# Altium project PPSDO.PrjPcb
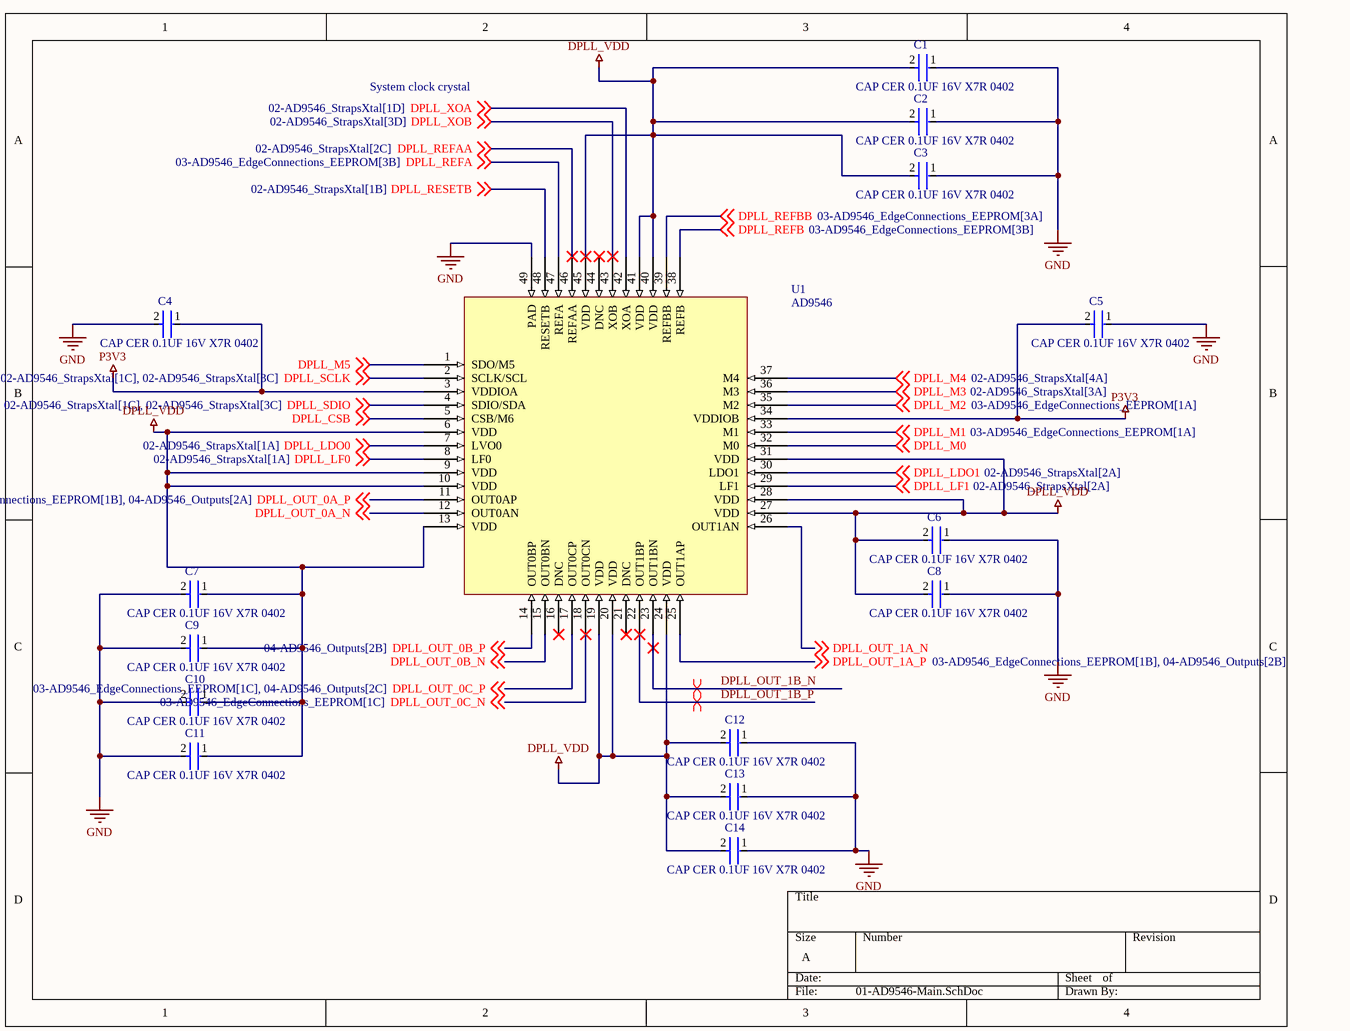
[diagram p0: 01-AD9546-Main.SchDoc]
5 sheets, 74 parts. Net scope: global (net labels, ports and power ports of the same name join across sheets).
Board file: PPSDO.PcbDoc
Sheets:
  01-AD9546-Main.SchDoc
  02-AD9546_StrapsXtal.SchDoc
  03-AD9546_EdgeConnections_EEPROM.SchDoc
  04-AD9546_Outputs.SchDoc
  05-Power.SchDoc

## Sheet 01-AD9546-Main.SchDoc
size A; SheetNumber: 4; SheetTotal: 16

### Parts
C1  GRM155R71C104KA88D  [FP-GRM15-MFG]  (value not drawn)
C2  GRM155R71C104KA88D  [FP-GRM15-MFG]  (value not drawn)
C3  GRM155R71C104KA88D  [FP-GRM15-MFG]  (value not drawn)
C4  GRM155R71C104KA88D  [FP-GRM15-MFG]  (value not drawn)
C5  GRM155R71C104KA88D  [FP-GRM15-MFG]  (value not drawn)
C6  GRM155R71C104KA88D  [FP-GRM15-MFG]  (value not drawn)
C7  GRM155R71C104KA88D  [FP-GRM15-MFG]  (value not drawn)
C8  GRM155R71C104KA88D  [FP-GRM15-MFG]  (value not drawn)
C9  GRM155R71C104KA88D  [FP-GRM15-MFG]  (value not drawn)
C10  GRM155R71C104KA88D  [FP-GRM15-MFG]  (value not drawn)
C11  GRM155R71C104KA88D  [FP-GRM15-MFG]  (value not drawn)
C12  GRM155R71C104KA88D  [FP-GRM15-MFG]  (value not drawn)
C13  GRM155R71C104KA88D  [FP-GRM15-MFG]  (value not drawn)
C14  GRM155R71C104KA88D  [FP-GRM15-MFG]  (value not drawn)
U1  AD9546  [AD9546]

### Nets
DPLL_VDD: C1.2 C2.2 C3.2 C6.2 C7.1 C8.2 C9.1 C10.1 C11.1 C12.2 C13.2 C14.2 U1.6(VDD) U1.9(VDD) U1.10(VDD) U1.13(VDD) U1.19(VDD) U1.20(VDD) U1.24(VDD) U1.27(VDD) U1.28(VDD) U1.31(VDD) U1.40(VDD) U1.41(VDD) U1.45(VDD)
GND: C1.1 C2.1 C3.1 C4.2 C5.1 C6.1 C7.2 C8.1 C9.2 C10.2 C11.2 C12.1 C13.1 C14.1 U1.49(PAD)
P3V3: C4.1 C5.2 U1.3(VDDIOA) U1.34(VDDIOB)
DPLL_CSB: U1.5(CSB/M6) ; off-sheet DPLL_CSB
DPLL_LDO0: U1.7(LVO0) ; off-sheet DPLL_LDO0
DPLL_LDO1: U1.30(LDO1) ; off-sheet DPLL_LDO1
DPLL_LF0: U1.8(LF0) ; off-sheet DPLL_LF0
DPLL_LF1: U1.29(LF1) ; off-sheet DPLL_LF1
DPLL_M0: U1.32(M0) ; off-sheet DPLL_M0
DPLL_M1: U1.33(M1) ; off-sheet DPLL_M1
DPLL_M2: U1.35(M2) ; off-sheet DPLL_M2
DPLL_M3: U1.36(M3) ; off-sheet DPLL_M3
DPLL_M4: U1.37(M4) ; off-sheet DPLL_M4
DPLL_M5: U1.1(SDO/M5) ; off-sheet DPLL_M5
DPLL_OUT_0A_N: U1.12(OUT0AN) ; off-sheet DPLL_OUT_0A_N
DPLL_OUT_0A_P: U1.11(OUT0AP) ; off-sheet DPLL_OUT_0A_P
DPLL_OUT_0B_N: U1.15(OUT0BN) ; off-sheet DPLL_OUT_0B_N
DPLL_OUT_0B_P: U1.14(OUT0BP) ; off-sheet DPLL_OUT_0B_P
DPLL_OUT_0C_N: U1.18(OUT0CN) ; off-sheet DPLL_OUT_0C_N
DPLL_OUT_0C_P: U1.17(OUT0CP) ; off-sheet DPLL_OUT_0C_P
DPLL_OUT_1A_N: U1.26(OUT1AN) ; off-sheet DPLL_OUT_1A_N
DPLL_OUT_1A_P: U1.25(OUT1AP) ; off-sheet DPLL_OUT_1A_P
DPLL_OUT_1B_N: U1.23(OUT1BN)
DPLL_OUT_1B_P: U1.22(OUT1BP)
DPLL_REFA: U1.47(REFA) ; off-sheet DPLL_REFA
DPLL_REFAA: U1.46(REFAA) ; off-sheet DPLL_REFAA
DPLL_REFB: U1.38(REFB) ; off-sheet DPLL_REFB
DPLL_REFBB: U1.39(REFBB) ; off-sheet DPLL_REFBB
DPLL_RESETB: U1.48(RESETB) ; off-sheet DPLL_RESETB
DPLL_SCLK: U1.2(SCLK/SCL) ; off-sheet DPLL_SCLK
DPLL_SDIO: U1.4(SDIO/SDA) ; off-sheet DPLL_SDIO
DPLL_XOA: U1.42(XOA) ; off-sheet DPLL_XOA
DPLL_XOB: U1.43(XOB) ; off-sheet DPLL_XOB

Not connected (* = marked no-connect by the designer): U1 16(DNC)* 21(DNC)* 44(DNC)*

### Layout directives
differential pair; differential pair class 100ohm: DPLL_OUT_1B_N, DPLL_OUT_1B_P

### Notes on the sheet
- System clock crystal

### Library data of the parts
C1-C14 = CMP-2100-03641-2: CAP CER 0.1UF 16V X7R 0402; Manufacturer: Murata; Standoff Height: 0mm; Tolerance: 10%; Voltage Rating: 16Vdc; Material: Ceramic; Capacitance: 0.10μF; Value: 0.10μF

## Sheet 02-AD9546_StrapsXtal.SchDoc
size A; SheetNumber: 5; SheetTotal: 16
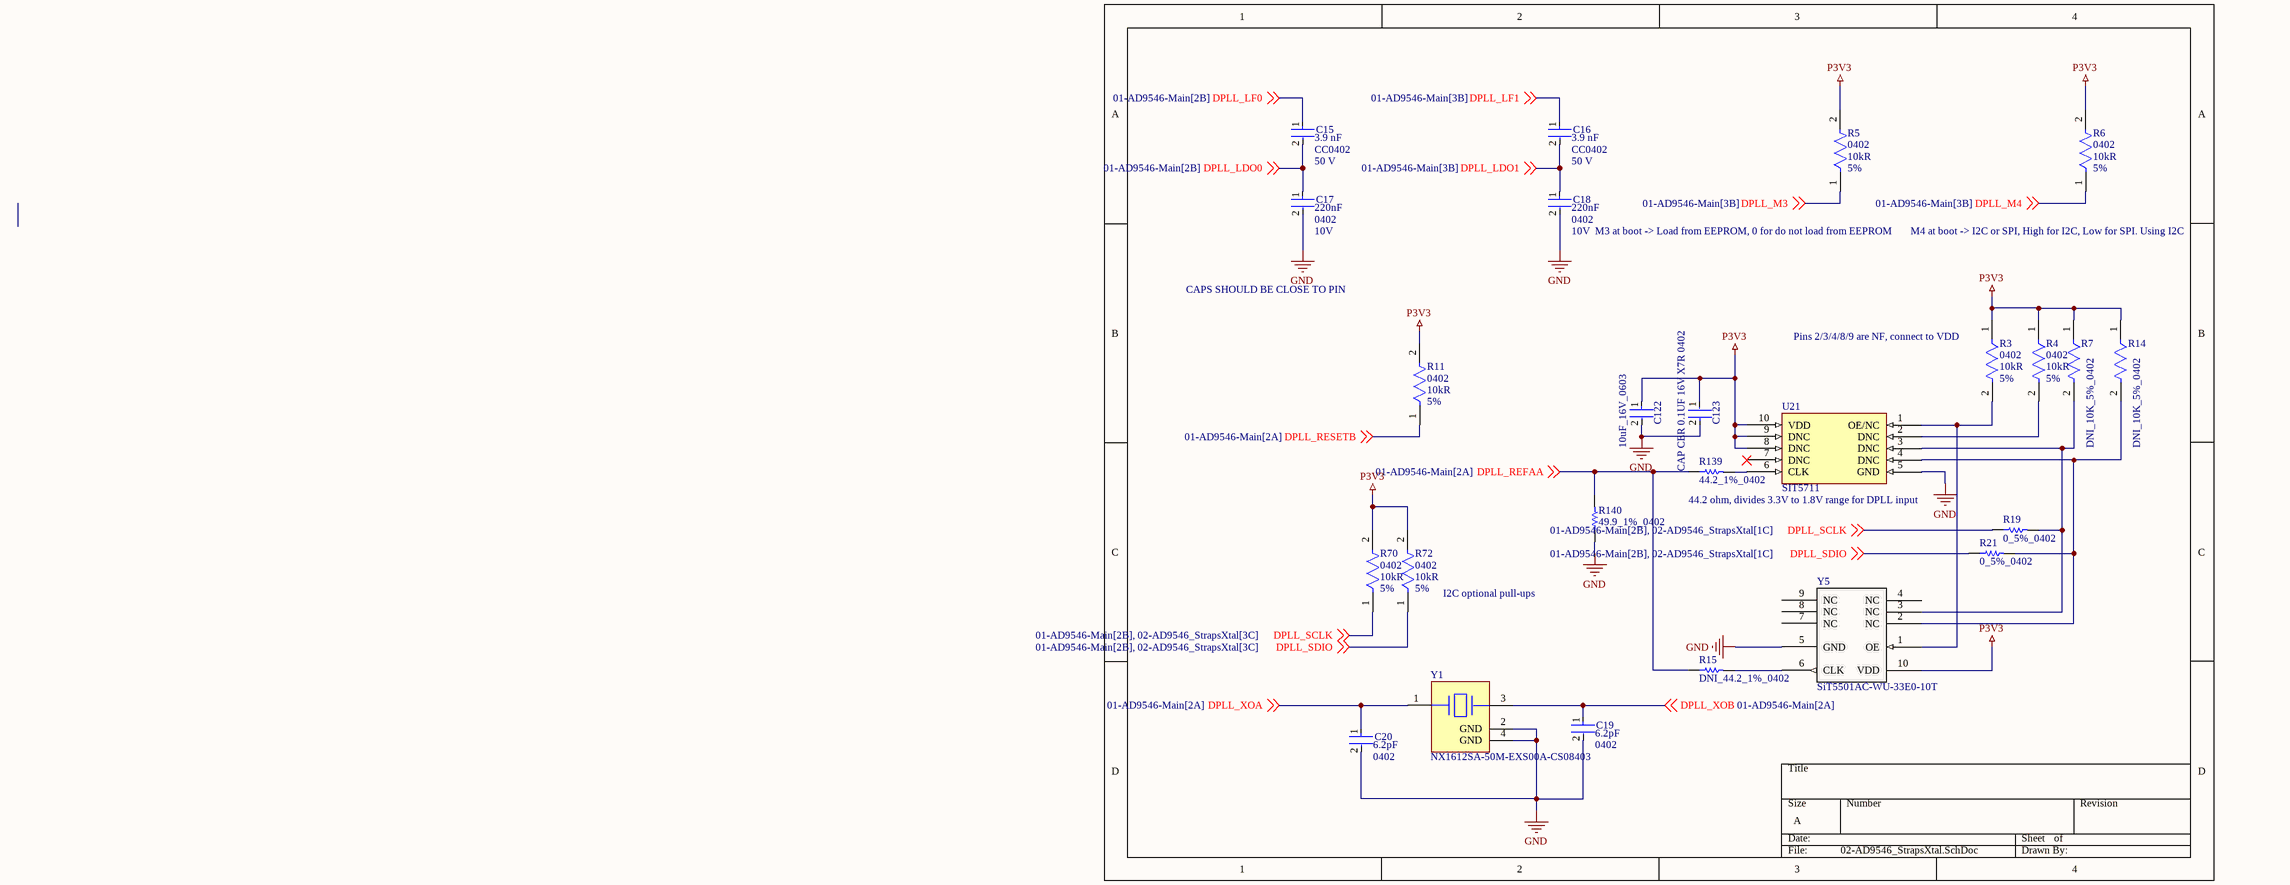
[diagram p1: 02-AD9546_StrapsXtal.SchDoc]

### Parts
C15  value 3.9 nF  Voltage Rating: 50 V  Package: CC0402  [FP-CC0402-MFG]  (hidden comment: CC0402KRX7R9BB392)
C16  value 3.9 nF  Voltage Rating: 50 V  Package: CC0402  [FP-CC0402-MFG]  (hidden comment: CC0402KRX7R9BB392)
C17  Voltage: 10V  Case/Package: 0402  Capacitance: 220nF  [FP-GRM155-0_05-IPC_A]  (hidden comment: GRM155R61A224KE19D)
C18  Voltage: 10V  Case/Package: 0402  Capacitance: 220nF  [FP-GRM155-0_05-IPC_A]  (hidden comment: GRM155R61A224KE19D)
C19  Case/Package: 0402  Capacitance: 6.2pF  [FP-CL468-IPC_C]  (hidden comment: CL05C6R2CB5NNNC)
C20  Case/Package: 0402  Capacitance: 6.2pF  [FP-CL468-IPC_C]  (hidden comment: CL05C6R2CB5NNNC)
C122  10uF_16V_0603  [FP-C1608-MFG]
C123  GRM155R71C104KA88D  [FP-GRM15-MFG]  (value not drawn)
R3  Case/Package: 0402  Resistance: 10kR  Tolerance: 5%  [FP-CRCW0402-e3-IPC_B]  (hidden comment: CRCW040210K0JNED)
R4  Case/Package: 0402  Resistance: 10kR  Tolerance: 5%  [FP-CRCW0402-e3-IPC_B]  (hidden comment: CRCW040210K0JNED)
R5  Case/Package: 0402  Resistance: 10kR  Tolerance: 5%  [FP-CRCW0402-e3-IPC_B]  (hidden comment: CRCW040210K0JNED)
R6  Case/Package: 0402  Resistance: 10kR  Tolerance: 5%  [FP-CRCW0402-e3-IPC_B]  (hidden comment: CRCW040210K0JNED)
R7  DNI_10K_5%_0402  [FP-CRCW0402-e3-IPC_B]  (no BOM)
R11  Case/Package: 0402  Resistance: 10kR  Tolerance: 5%  [FP-CRCW0402-e3-IPC_B]  (hidden comment: CRCW040210K0JNED)
R14  DNI_10K_5%_0402  [FP-CRCW0402-e3-IPC_B]  (no BOM)
R15  DNI_44.2_1%_0402  [RESC0402(1005)_M]  (no BOM)
R19  0_5%_0402  [RESC1005X40X25NL05T10]
R21  0_5%_0402  [RESC1005X40X25NL05T10]
R70  Case/Package: 0402  Resistance: 10kR  Tolerance: 5%  [FP-CRCW0402-e3-IPC_B]  (hidden comment: CRCW040210K0JNED)
R72  Case/Package: 0402  Resistance: 10kR  Tolerance: 5%  [FP-CRCW0402-e3-IPC_B]  (hidden comment: CRCW040210K0JNED)
R139  44.2_1%_0402  [RESC0402(1005)_M]
R140  49.9_1%_0402  [RESC1005X40X25NL05T05]
U21  SIT5711  [SIT5711]  (no BOM)
Y1  NX1612SA-50M-EXS00A-CS08403  [FP-NX1612SA-MFG]
Y5  Manufacturer Part Number: SiT5501AC-WU-33E0-10T  [SITIME_SPL-086-CQFN-010-C07050_REV_DRAFT]  (hidden comment: SiTime_SiT5501AC-WU-33E0-10T)  (no BOM)

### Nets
GND: C17.2 C18.2 C19.2 C20.2 C122.2 C123.2 R140.1 U21.5(GND) Y1.2(GND) Y1.4(GND) Y5.5(GND)
P3V3: C122.1 C123.1 R3.1 R4.1 R5.2 R6.2 R7.1 R11.2 R14.1 R70.2 R72.2 U21.8(DNC) U21.9(DNC) U21.10(VDD) Y5.10(VDD)
DPLL_LDO0: C15.2 C17.1 ; off-sheet DPLL_LDO0
DPLL_LDO1: C16.2 C18.1 ; off-sheet DPLL_LDO1
DPLL_LF0: C15.1 ; off-sheet DPLL_LF0
DPLL_LF1: C16.1 ; off-sheet DPLL_LF1
DPLL_M3: R5.1 ; off-sheet DPLL_M3
DPLL_M4: R6.1 ; off-sheet DPLL_M4
DPLL_REFAA: R15.1 R139.1 R140.2 ; off-sheet DPLL_REFAA
DPLL_RESETB: R11.1 ; off-sheet DPLL_RESETB
DPLL_SCLK: R19.1 R70.1 ; off-sheet DPLL_SCLK
DPLL_SDIO: R21.1 R72.1 ; off-sheet DPLL_SDIO
DPLL_XOA: C20.1 Y1.1(1_Xtal) ; off-sheet DPLL_XOA
DPLL_XOB: C19.1 Y1.3(2_Xtal) ; off-sheet DPLL_XOB
NetR3_2: R3.2 U21.1(OE/NC) Y5.1(OE)
NetR4_2: R4.2 U21.2(DNC)
NetR7_2: R7.2 R19.2 U21.3(DNC) Y5.3(NC)
NetR14_2: R14.2 R21.2 U21.4(DNC) Y5.2(NC)
NetR15_2: R15.2 Y5.6(CLK)
NetR139_2: R139.2 U21.6(CLK)

Not connected (* = marked no-connect by the designer): U21 7(DNC)*; Y5 4(NC) 7(NC) 8(NC) 9(NC)

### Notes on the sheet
- M3 at boot -> Load from EEPROM, 0 for do not load from EEPROM
- M4 at boot -> I2C or SPI, High for I2C, Low for SPI. Using I2C
- CAPS SHOULD BE CLOSE TO PIN
- (near R3) Pins 2/3/4/8/9 are NF, connect to VDD
- 44.2 ohm, divides 3.3V to 1.8V range for DPLL input
- (near R72) I2C optional pull-ups

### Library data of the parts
C15 C16 = CMP-03422-000890-1: CAP CER 3900PF 50V X7R 0402; Manufacturer: YAGEO; Tolerance: 0.1; Temperature Coefficient: 30ppm/°C; Material: Ceramic; Automotive Grade: NA
C17 C18 = CMP-2008-04561-5: CAP CER 0.22UF 10V X5R 0402; Tolerance: 10%; Material: Ceramic; Insulation Resistance: 10GR
C19 C20 = CMP-13271-000420-1: Cap Ceramic 6.2pF 50V C0G ±0.25pF SMD 0402 +125°C Paper T/R
C122 = CMP-08246-000019-1: CAP CER 10UF 16V X5R 0603; Manufacturer: TDK Corporation; Manufacturer Part Number: C1608X5R1C106M080AB; Temperature Coefficient: 15%; Tolerance: 20%; Material: Ceramic
C123 = CMP-2100-03641-2: as C1 on sheet 01-AD9546-Main
R3-R6 R11 R70 R72 = CMP-2002-08136-3: RES Thick Film, 10kΩ, 5%, 0.063W, 200ppm/°C, 0402; Voltage Rating: 50V; Power Rating: 63mW
R7 R14 = CMP-2002-08136-3: RES Thick Film, 10kΩ, 5%, 0.063W, 200ppm/°C, 0402; Voltage Rating: 50V; Power Rating: 63mW; Resistance: 10kR
R15 R139 = CMP-1011-00357-1: 44R2 0.063W 1% 0402 (1005 Metric)  SMD; Case-Metric: 1005; Value: 44.20 Ohm; Case-EIA: 0402
R19 R21 = CMP-1011-00001-2: Manufacturer: Yageo / Phycomp; Part Number: RC0402JR-070RL
R140 = CMP-2002-00969-1: Manufacturer: Panasonic; Part Number: ERJ-2RKF49R9X
Y1 = CMP-200220-000009-1: CRYSTAL 50MHZ 8PF SMD; ESR (Equivalent Series Resistance): 80R; Frequency Stability: 15ppm; Frequency Tolerance: 10ppm
Y5 = CMP-OSC-00029-2: OSC, MEMS, STRATUM 3E, 10.000MHZ, 10PPB STAB, LVCMOS, 3.3V, O/P EN, 7.0X5.0X2.2MM, CQFN-10; Internal Part Number: 820-00386-00; Manufacturer: SiTime; Frequency: 10 MHz

## Sheet 03-AD9546_EdgeConnections_EEPROM.SchDoc
size A; SheetNumber: 6; SheetTotal: 16
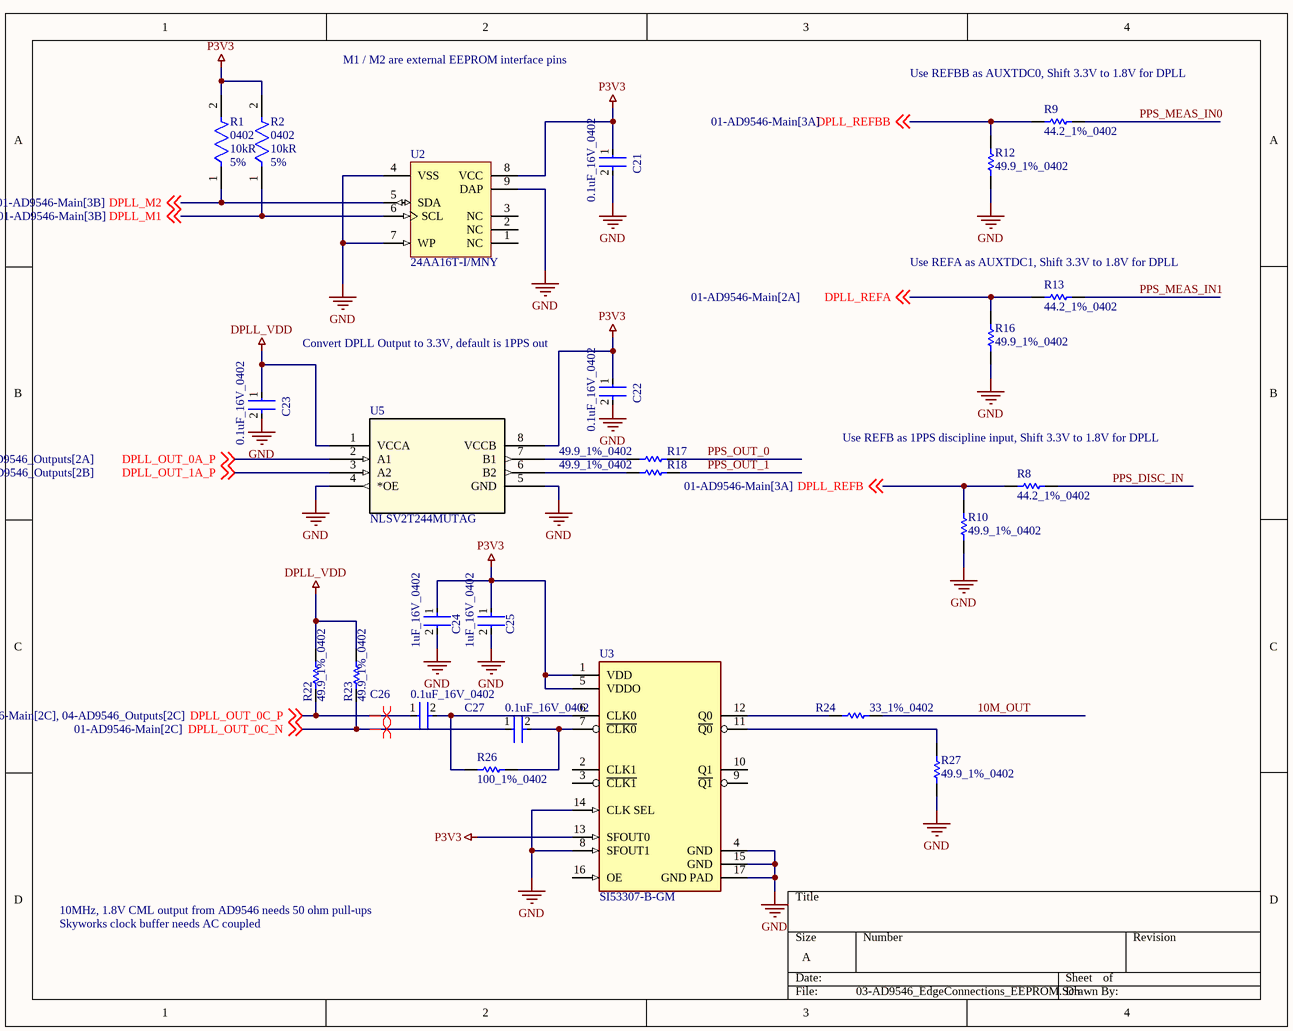
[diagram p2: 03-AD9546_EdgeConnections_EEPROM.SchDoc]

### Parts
C21  0.1uF_16V_0402  [FP-GRM15-MFG]
C22  0.1uF_16V_0402  [FP-GRM15-MFG]
C23  0.1uF_16V_0402  [FP-GRM15-MFG]
C24  1uF_16V_0402  [FP-0402-L_1_0_0_05-W_0_5-IPC_C]
C25  1uF_16V_0402  [FP-0402-L_1_0_0_05-W_0_5-IPC_C]
C26  0.1uF_16V_0402  [FP-GRM15-MFG]
C27  0.1uF_16V_0402  [FP-GRM15-MFG]
R1  Case/Package: 0402  Resistance: 10kR  Tolerance: 5%  [FP-CRCW0402-e3-IPC_B]  (hidden comment: CRCW040210K0JNED)
R2  Case/Package: 0402  Resistance: 10kR  Tolerance: 5%  [FP-CRCW0402-e3-IPC_B]  (hidden comment: CRCW040210K0JNED)
R8  44.2_1%_0402  [RESC1005X40X25LL05T05]
R9  44.2_1%_0402  [RESC1005X40X25LL05T05]
R10  49.9_1%_0402  [RESC1005X40X25NL05T05]
R12  49.9_1%_0402  [RESC1005X40X25NL05T05]
R13  44.2_1%_0402  [RESC1005X40X25LL05T05]
R16  49.9_1%_0402  [RESC1005X40X25NL05T05]
R17  49.9_1%_0402  [RESC1005X40X25NL05T05]
R18  49.9_1%_0402  [RESC1005X40X25NL05T05]
R22  49.9_1%_0402  [RESC1005X40X25NL05T05]
R23  49.9_1%_0402  [RESC1005X40X25NL05T05]
R24  33_1%_0402  [RESC1005X40X25LL05T10]
R26  100_1%_0402  [RESC1005X40X25ML05T10]
R27  49.9_1%_0402  [RESC1005X40X25NL05T05]
U2  24AA16T-I/MNY  [TDFN-MN8]
U3  SI53307-B-GM  [FP-SI53307-B-GM-MFG]
U5  NLSV2T244MUTAG  [UDFN8_1P20X1P80_ONS]

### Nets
DPLL_VDD: C23.1 R22.1 R23.1 U5.1(VCCA)
GND: C21.2 C22.2 C23.2 C24.2 C25.2 R10.1 R12.1 R16.1 R27.2 U2.4(VSS) U2.7(WP) U2.9(DAP) U3.4(GND) U3.8(SFOUT1) U3.14(CLK_SEL) U3.15(GND) U3.17(GND_PAD) U5.4(*OE) U5.5(GND)
P3V3: C21.1 C22.1 C24.1 C25.1 R1.2 R2.2 U2.8(VCC) U3.1(VDD) U3.5(VDDO) U3.13(SFOUT0) U5.8(VCCB)
10M_OUT: R24.2
DPLL_M1: R2.1 U2.6(SCL) ; off-sheet DPLL_M1
DPLL_M2: R1.1 U2.5(SDA) ; off-sheet DPLL_M2
DPLL_OUT_0A_P: U5.2(A1) ; off-sheet DPLL_OUT_0A_P
DPLL_OUT_0C_N: C27.1 R23.2 ; off-sheet DPLL_OUT_0C_N
DPLL_OUT_0C_P: C26.1 R22.2 ; off-sheet DPLL_OUT_0C_P
DPLL_OUT_1A_P: U5.3(A2) ; off-sheet DPLL_OUT_1A_P
DPLL_REFA: R13.1 R16.2 ; off-sheet DPLL_REFA
DPLL_REFB: R8.1 R10.2 ; off-sheet DPLL_REFB
DPLL_REFBB: R9.1 R12.2 ; off-sheet DPLL_REFBB
PPS_DISC_IN: R8.2
PPS_MEAS_IN0: R9.2
PPS_MEAS_IN1: R13.2
PPS_OUT_0: R17.1
PPS_OUT_1: R18.1
NetC26_2: C26.2 R26.1 U3.6(CLK0)
NetC27_2: C27.2 R26.2 U3.7(~{CLK0})
NetR17_2: R17.2 U5.7(B1)
NetR18_2: R18.2 U5.6(B2)
NetR24_1: R24.1 U3.12(Q0)
NetR27_1: R27.1 U3.11(~{Q0})

Not connected (* = marked no-connect by the designer): U2 1(NC) 2(NC) 3(NC); U3 2(CLK1) 3(~{CLK1}) 9(~{Q1}) 10(Q1) 16(OE)

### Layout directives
differential pair: DPLL_OUT_0C_N, DPLL_OUT_0C_P

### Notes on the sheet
- M1 / M2 are external EEPROM interface pins
- (near R9) Use REFBB as AUXTDC0, Shift 3.3V to 1.8V for DPLL
- (near R13) Use REFA as AUXTDC1, Shift 3.3V to 1.8V for DPLL
- Convert DPLL Output to 3.3V, default is 1PPS out
- (near R8) Use REFB as 1PPS discipline input, Shift 3.3V to 1.8V for DPLL
- 10MHz, 1.8V CML output from AD9546 needs 50 ohm pull-ups
- Skyworks clock buffer needs AC coupled

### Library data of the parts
C21-C23 C26 C27 = CMP-2100-03641-2: CAP CER 0.1UF 16V X7R 0402; Manufacturer Part Number: GRM155R71C104KA88D; Manufacturer: Murata; Standoff Height: 0mm; Tolerance: 10%; Voltage Rating: 16Vdc; Material: Ceramic; Capacitance: 0.10μF; Value: 0.10μF
C24 C25 = CMP-14477-003537-2: None; Tolerance: 20%; Voltage Rating (DC): 16V; Capacitance: 1uF; Dielectric: X5R
R1 R2 = CMP-2002-08136-3: as R3 on sheet 02-AD9546_StrapsXtal
R8 R9 R13 = CMP-2002-00011-1: Manufacturer: Vishay Dale; Part Number: CRCW040244R2FKED
R10 R12 R16-R18 R22 R23 R27 = CMP-2002-00969-1: as R140 on sheet 02-AD9546_StrapsXtal
R24 = CMP-2002-07619-1: Part Number: RC0402FR-0733RL; Manufacturer: Yageo / Phycomp
R26 = CMP-2002-07344-1: Part Number: RC0402FR-07100RL; Manufacturer: Yageo / Phycomp
U2 = CMP-0159-00483-1: 16Kbit, 400kHz, 1.7V, I2C Serial EEPROM, 8-Pin TDFN (NiPdAu finish), Industrial Temperature, Tape and Reel
U3 = CMP-08071-000001-1: IC CLK BUFFER 2:4 725MHZ 16QFN; Manufacturer: Silicon Labs; Number Of Inputs: 2; Standoff Height: 0mm; Number Of Outputs: 4; Max Junction Temp: +125°C; Description: Clock Fanout Buffer (Distribution), Multiplexer IC 2:4 725MHz 16-VFQFN Exposed Pad; Min Supply Voltage: 1.71V; Number Of Elements: 1; Nominal Supply Current: 65mA; Max Supply Voltage: 3.63V; Logic Function: Non-Inverting; Propagation Delay: 875ps
U5 = NLSV2T244MUTAG: No Description Available; Mfr_Name: onsemi

## Sheet 04-AD9546_Outputs.SchDoc
size A; SheetNumber: 7; SheetTotal: 16
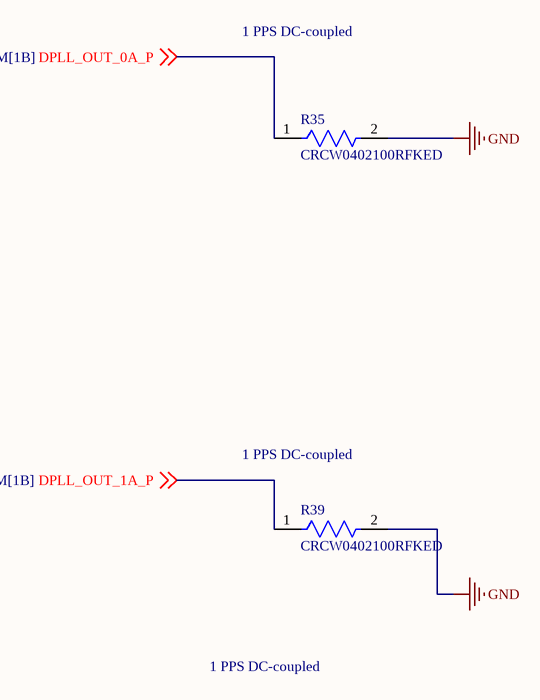
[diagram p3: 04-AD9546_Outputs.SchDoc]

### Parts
R35  CRCW0402100RFKED  [FP-CRCW0402-e3-IPC_C]
R39  CRCW0402100RFKED  [FP-CRCW0402-e3-IPC_C]

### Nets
GND: R35.2 R39.2
DPLL_OUT_0A_P: R35.1 ; off-sheet DPLL_OUT_0A_P
DPLL_OUT_1A_P: R39.1 ; off-sheet DPLL_OUT_1A_P

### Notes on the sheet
- 1 PPS DC-coupled

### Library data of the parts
R35 R39 = CMP-1011-00397-3: RES Thick Film, 100Ω, 1%, 0.063W, 100ppm/°C, 0402; Max Power Dissipation: 63mW; Voltage Rating: 50V; Resistance: 100R

## Sheet 05-Power.SchDoc
size A; SheetNumber: 16; SheetTotal: 16
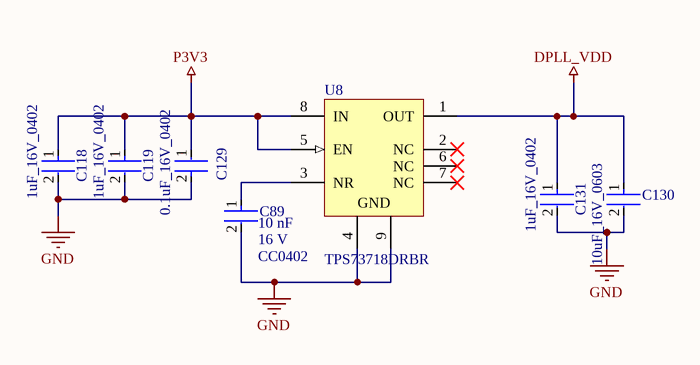
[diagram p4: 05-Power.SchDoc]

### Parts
C89  value 10 nF  Package: CC0402  Voltage Rating: 16 V  [FP-CC0402-MFG]  (hidden comment: CC0402KRX7R7BB103)
C118  1uF_16V_0402  [FP-0402-L_1_0_0_05-W_0_5-IPC_C]
C119  1uF_16V_0402  [FP-0402-L_1_0_0_05-W_0_5-IPC_C]
C129  0.1uF_16V_0402  [FP-GRM15-MFG]
C130  10uF_16V_0603  [FP-MK107BA-IPC_A]
C131  1uF_16V_0402  [FP-0402-L_1_0_0_05-W_0_5-IPC_C]
U8  TPS73718DRBR  [DRB0008A_V]

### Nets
DPLL_VDD: C130.1 C131.1 U8.1(OUT)
GND: C89.2 C118.2 C119.2 C129.2 C130.2 C131.2 U8.4(GND) U8.9(GND)
P3V3: C118.1 C119.1 C129.1 U8.5(EN) U8.8(IN)
NetC89_1: C89.1 U8.3(NR)

Not connected (* = marked no-connect by the designer): U8 2(NC)* 6(NC)* 7(NC)*

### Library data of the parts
C89 = CMP-03422-000501-1: CAP CER 10000PF 16V X7R 0402; Manufacturer: YAGEO; Automotive Grade: NA; Material: Ceramic; Tolerance: 0.1; Temperature Coefficient: 30ppm/°C
C118 C119 C131 = CMP-14477-003537-2: as C24 on sheet 03-AD9546_EdgeConnections_EEPROM
C129 = CMP-2100-03641-2: as C21 on sheet 03-AD9546_EdgeConnections_EEPROM
C130 = CMP-2000-06226-3: None; Dielectric: X5R; Voltage Rating: 16V; Tolerance: 20%; Capacitance: 10uF
U8 = CMP-0395-00613-2: Single Output LDO, 1 A, Fixed 1.8 V Output, 2.2 to 5.5 V Input, with Reverse Current Protection, 8-pin SON (DRB), -40 to 125 degC, Green (RoHS & no Sb/Br); Manufacturer: Texas Instruments; Fixed Output Options(V): 1.8; Vin(Min)(V): 2.2; Iq(Typ)(mA): 0.3; Accuracy(%): 3; Vdo(Typ)(mV): 130; SubFamily: Single Channel LDO; Vin(Max)(V): 5.5; Iout(Max)(A): 1; Rating: Catalog

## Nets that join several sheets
DPLL_VDD: 01-AD9546-Main (25 pins), 03-AD9546_EdgeConnections_EEPROM (C23.1 R22.1 R23.1 U5.1), 05-Power (C130.1 C131.1 U8.1)
GND: 01-AD9546-Main (15 pins), 02-AD9546_StrapsXtal (11 pins), 03-AD9546_EdgeConnections_EEPROM (19 pins), 04-AD9546_Outputs (R35.2 R39.2), 05-Power (8 pins)
P3V3: 01-AD9546-Main (C4.1 C5.2 U1.3 U1.34), 02-AD9546_StrapsXtal (15 pins), 03-AD9546_EdgeConnections_EEPROM (11 pins), 05-Power (5 pins)
DPLL_LDO0: 01-AD9546-Main (U1.7), 02-AD9546_StrapsXtal (C15.2 C17.1)
DPLL_LDO1: 01-AD9546-Main (U1.30), 02-AD9546_StrapsXtal (C16.2 C18.1)
DPLL_LF0: 01-AD9546-Main (U1.8), 02-AD9546_StrapsXtal (C15.1)
DPLL_LF1: 01-AD9546-Main (U1.29), 02-AD9546_StrapsXtal (C16.1)
DPLL_M1: 01-AD9546-Main (U1.33), 03-AD9546_EdgeConnections_EEPROM (R2.1 U2.6)
DPLL_M2: 01-AD9546-Main (U1.35), 03-AD9546_EdgeConnections_EEPROM (R1.1 U2.5)
DPLL_M3: 01-AD9546-Main (U1.36), 02-AD9546_StrapsXtal (R5.1)
DPLL_M4: 01-AD9546-Main (U1.37), 02-AD9546_StrapsXtal (R6.1)
DPLL_OUT_0A_P: 01-AD9546-Main (U1.11), 03-AD9546_EdgeConnections_EEPROM (U5.2), 04-AD9546_Outputs (R35.1)
DPLL_OUT_0C_N: 01-AD9546-Main (U1.18), 03-AD9546_EdgeConnections_EEPROM (C27.1 R23.2)
DPLL_OUT_0C_P: 01-AD9546-Main (U1.17), 03-AD9546_EdgeConnections_EEPROM (C26.1 R22.2)
DPLL_OUT_1A_P: 01-AD9546-Main (U1.25), 03-AD9546_EdgeConnections_EEPROM (U5.3), 04-AD9546_Outputs (R39.1)
DPLL_REFA: 01-AD9546-Main (U1.47), 03-AD9546_EdgeConnections_EEPROM (R13.1 R16.2)
DPLL_REFAA: 01-AD9546-Main (U1.46), 02-AD9546_StrapsXtal (R15.1 R139.1 R140.2)
DPLL_REFB: 01-AD9546-Main (U1.38), 03-AD9546_EdgeConnections_EEPROM (R8.1 R10.2)
DPLL_REFBB: 01-AD9546-Main (U1.39), 03-AD9546_EdgeConnections_EEPROM (R9.1 R12.2)
DPLL_RESETB: 01-AD9546-Main (U1.48), 02-AD9546_StrapsXtal (R11.1)
DPLL_SCLK: 01-AD9546-Main (U1.2), 02-AD9546_StrapsXtal (R19.1 R70.1)
DPLL_SDIO: 01-AD9546-Main (U1.4), 02-AD9546_StrapsXtal (R21.1 R72.1)
DPLL_XOA: 01-AD9546-Main (U1.42), 02-AD9546_StrapsXtal (C20.1 Y1.1)
DPLL_XOB: 01-AD9546-Main (U1.43), 02-AD9546_StrapsXtal (C19.1 Y1.3)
